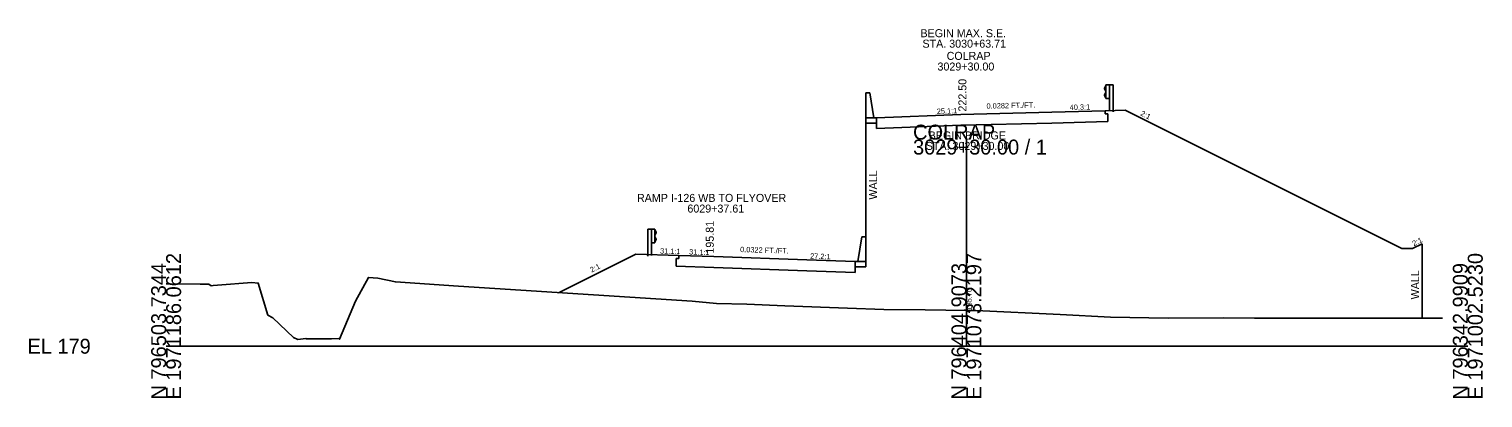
# Model space of a CAD drawing. Extents: x -26 to 1971073, y -10 to 796405.
# Drawn here: x -25.7 to 246.8, y -9.7 to 59.5 of the extents above; entities that cross this region are included whole.
import ezdxf

# ---------------------------------------------------------------- set-up
doc = ezdxf.new("R2010")
doc.units = 0
for name, color, linetype in [('RD_GPK_XS_Cell', 7, 'Continuous'), ('RD_XS_Base', 7, 'Continuous'), ('RD_XS_Box', 7, 'Continuous'), ('RD_XS_EarthShd', 7, 'Continuous'), ('RD_XS_ExGround', 7, 'Continuous'), ('RD_XS_GR', 7, 'Continuous'), ('RD_XS_MedBWall', 7, 'Continuous'), ('RD_XS_Pave', 7, 'Continuous'), ('RD_XS_PaveShd', 7, 'Continuous'), ('RD_XS_TieSlope', 7, 'Continuous'), ('RD_XS_TX_Elev_EX', 7, 'Continuous'), ('RD_XS_TX_Elev_PR', 7, 'Continuous'), ('RD_XS_TX_Notes', 7, 'Continuous'), ('RD_XS_TX_ShdSlope', 7, 'Continuous'), ('RD_XS_TX_Slope', 7, 'Continuous'), ('RD_XS_TX_Station', 7, 'Continuous')]:
    doc.layers.add(name, color=color, linetype=linetype)

msp = doc.modelspace()

# ---------------------------------------------------------------- linework, layer by layer
at = {"layer": 'RD_GPK_XS_Cell'}
for p, q in [((150, 0), (150, 38.74)), ((0, 0), (150, 0)), ((150, 0), (243.98, 0))]:
    msp.add_line(p, q, dxfattribs=at)
at = {"layer": 'RD_XS_Base'}
for p, q in [((176, 43.58), (176, 44.14)), ((133.16, 40.8), (133.16, 42.84)), ((148.97, 41.43), (133.16, 40.8)), ((148.97, 41.43), (166, 41.85)), ((166, 41.85), (176.5, 42.11)), ((176.5, 43.59), (176, 43.58)), ((176.5, 42.11), (176.5, 43.59)), ((95.57, 16.48), (96.12, 16.46)), ((95.57, 15), (95.57, 16.48)), ((96.12, 16.46), (96.12, 17.02)), ((102.65, 14.77), (95.57, 15)), ((102.65, 14.77), (120.09, 14.16)), ((120.09, 14.16), (129.16, 13.83)), ((129.16, 13.83), (129.16, 15.87))]:
    msp.add_line(p, q, dxfattribs=at)
at = {"layer": 'RD_XS_Box'}
for p, q in [((131.16, 42.84), (131.16, 15.87)), ((133.16, 42.84), (131.16, 42.84)), ((235.43, 19.22), (235.43, 5.27)), ((131.16, 15.87), (129.16, 15.87))]:
    msp.add_line(p, q, dxfattribs=at)
at = {"layer": 'RD_XS_EarthShd'}
for p, q in [((176, 44.14), (179.75, 44.23)), ((96.12, 17.02), (88.01, 17.28))]:
    msp.add_line(p, q, dxfattribs=at)
at = {"layer": 'RD_XS_ExGround'}
msp.add_line((203.98, 5.27), (239.27, 5.27), dxfattribs=at)
msp.add_lwpolyline([(0, 11.72), (0.51, 11.72), (6.36, 11.66), (8, 11.64), (8.43, 11.32), (8.83, 11.36), (9.62, 11.46), (16.06, 11.93), (17.26, 11.84), (19.05, 5.85), (20, 5.31), (23.87, 1.63), (24.7, 1.25), (26.16, 1.48), (26.32, 1.36), (29.6, 1.36), (30.97, 1.36), (32.38, 1.46), (32.51, 1.31), (35.47, 8.48), (37.9, 12.91), (39.69, 12.75), (42.97, 12.06), (54.8, 11.26), (98.59, 8.42), (103.13, 8), (108.85, 7.87), (115.97, 7.59), (127.7, 7.11), (134.5, 6.89), (142.27, 6.82), (150, 6.7), (151.75, 6.67), (167.58, 5.92), (177.02, 5.45), (187.8, 5.28), (198.13, 5.32), (203.98, 5.27)], dxfattribs=at)
at = {"layer": 'RD_XS_GR'}
for p, q in [((176.15, 48.84), (175.87, 48.4)), ((175.87, 48.4), (175.87, 48.29)), ((175.87, 48.29), (176.15, 47.85)), ((175.87, 47.14), (176.15, 47.58)), ((175.87, 47.03), (175.87, 47.14)), ((176.15, 46.59), (175.87, 47.03)), ((176.15, 49), (176.81, 49)), ((176.15, 46.43), (176.15, 49)), ((176.15, 46.43), (176.81, 46.43)), ((176.81, 49), (177.48, 49)), ((176.81, 49), (176.81, 44.06)), ((177.48, 49), (177.48, 43.95)), ((90.95, 21.96), (90.28, 21.96)), ((90.28, 21.96), (90.28, 16.9)), ((91.61, 21.96), (90.95, 21.96)), ((90.95, 21.96), (90.95, 17.02)), ((91.61, 19.39), (91.61, 21.96)), ((91.61, 19.39), (90.95, 19.39)), ((91.61, 21.8), (91.88, 21.36)), ((91.88, 21.25), (91.61, 20.81)), ((91.88, 20.1), (91.61, 20.54)), ((91.61, 19.55), (91.88, 19.99)), ((91.88, 21.36), (91.88, 21.25)), ((91.88, 19.99), (91.88, 20.1))]:
    msp.add_line(p, q, dxfattribs=at)
at = {"layer": 'RD_XS_MedBWall'}
for p, q in [((131.91, 47.5), (131.16, 47.5)), ((131.16, 47.5), (131.16, 41.84)), ((132.66, 42.84), (131.91, 47.5)), ((131.16, 41.84), (133.16, 41.84)), ((133.16, 42.84), (132.66, 42.84)), ((133.16, 41.84), (133.16, 42.84)), ((129.66, 15.87), (130.41, 20.54)), ((130.41, 20.54), (131.16, 20.54)), ((131.16, 20.54), (131.16, 14.87)), ((129.16, 14.87), (129.16, 15.87)), ((129.16, 15.87), (129.66, 15.87)), ((131.16, 14.87), (129.16, 14.87))]:
    msp.add_line(p, q, dxfattribs=at)
at = {"layer": 'RD_XS_Pave'}
for p, q in [((166, 43.89), (148.97, 43.47)), ((120.09, 16.2), (102.65, 16.81))]:
    msp.add_line(p, q, dxfattribs=at)
at = {"layer": 'RD_XS_PaveShd'}
for p, q in [((166, 43.89), (176, 44.14)), ((148.97, 43.47), (133.16, 42.84)), ((102.65, 16.81), (96.12, 17.02)), ((120.09, 16.2), (129.16, 15.87))]:
    msp.add_line(p, q, dxfattribs=at)
at = {"layer": 'RD_XS_TieSlope'}
for p, q in [((179.75, 44.23), (231.59, 18.31)), ((235.43, 19.22), (233.59, 18.31)), ((88.01, 17.28), (73.53, 10.04)), ((231.59, 18.31), (233.59, 18.31))]:
    msp.add_line(p, q, dxfattribs=at)

# ---------------------------------------------------------------- texts
at = {"layer": 'RD_GPK_XS_Cell'}
for s, p in [('COLRAP', (140, 38.74)), ('3029+30.00 / 1', (140, 35.94)), ('EL 179', (-26, -1.4))]:
    msp.add_text(s, height=2.8, dxfattribs=at).set_placement(p)
for s, p in [('E 1971186.0612', (2.8, -10)), ('E 1971073.2197', (152.8, -10)), ('E 1971002.5230', (246.78, -10)), ('N 796503.7344', (0, -10)), ('N 796404.9073', (150, -10)), ('N 796342.9909', (243.98, -10))]:
    msp.add_text(s, height=2.8, rotation=90, dxfattribs=at).set_placement(p)
at = {"layer": 'RD_XS_TX_Elev_EX'}
msp.add_text('185.70', height=1, rotation=90, dxfattribs=at).set_placement((151, 6.7))
at = {"layer": 'RD_XS_TX_Elev_PR'}
for s, p in [(' 222.50', (150, 43.44)), (' 195.81', (102.65, 16.81))]:
    msp.add_text(s, height=1.5, rotation=90, dxfattribs=at).set_placement(p)
at = {"layer": 'RD_XS_TX_Notes'}
for s, p in [('BEGIN MAX. S.E.', (141.39, 57.94)), ('STA. 3030+63.71', (141.76, 55.98)), ('STA. 3029+30.00', (142.38, 36.81)), ('BEGIN BRIDGE', (142.93, 38.77))]:
    msp.add_text(s, height=1.5, dxfattribs=at).set_placement(p)
for p in [(133.26, 27.5), (234.85, 8.79)]:
    msp.add_text('WALL', height=1.5, rotation=90, dxfattribs=at).set_placement(p)
at = {"layer": 'RD_XS_TX_ShdSlope'}
msp.add_text('31.1:1', height=1, rotation=358.157, dxfattribs=at).set_placement((92.56, 17.39))
at = {"layer": 'RD_XS_TX_Slope'}
for s, rotation, p in [('25.1:1', 2.285, (144.47, 43.54)), ('0.0282 FT./FT.', 1.4199, (153.78, 44.53)), ('40.3:1', 1.4199, (169.37, 44.29)), ('2:1', 333.4349, (182.52, 43.34)), ('2:1', 26.5651, (233.88, 18.73)), ('31.1:1', 358.157, (98.01, 17.21)), ('0.0322 FT./FT.', 358.157, (107.57, 17.66)), ('27.2:1', 357.8975, (120.7, 16.43)), ('2:1', 26.5651, (79.76, 13.79))]:
    msp.add_text(s, height=1, rotation=rotation, dxfattribs=at).set_placement(p)
at = {"layer": 'RD_XS_TX_Station'}
for s, p in [('COLRAP', (146.29, 53.69)), ('3029+30.00', (144.58, 51.69)), ('RAMP I-126 WB TO FLYOVER', (88.25, 27.06)), ('6029+37.61', (97.7, 25.06))]:
    msp.add_text(s, height=1.5, dxfattribs=at).set_placement(p)

doc.saveas('drawing.dxf')
